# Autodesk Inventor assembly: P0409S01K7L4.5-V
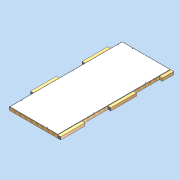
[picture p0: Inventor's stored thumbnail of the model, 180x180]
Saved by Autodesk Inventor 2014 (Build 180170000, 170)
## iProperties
Created: 2011-04
Part Number: P0409S01K7L4.5-V
Document SubType Name: Assembly
Designer: david.appleford
Description: 1w x 2.25w 01 Panel - 7 Locks 4.5 Lugs
Mass: 51000 g
Surface Area: 75539.4 cm^2
Volume: 258132 cm^3
Density: 0.197573 g/cm^3
Cost Center: £173.00
Justset: False
Title: 1w x 2.25w 01 Panel - 7 Locks 4.5 Lugs
Author: david.appleford
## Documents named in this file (5)
- C:\Documents and Settings\john.everitt\Local Settings\My Documents\Vault\Production MkII\VIRTUAL ELEMENTS\Virtual Walls\Virtual Timber + MgO\P0409S01K7L4.5-V.iam
- C:\Documents and Settings\john.everitt\Local Settings\My Documents\Vault\Production MkII\VIRTUAL ELEMENTS\Virtual Lugs\Superceded Lugs\LA02C3V.ipt
- C:\Documents and Settings\john.everitt\Local Settings\My Documents\Vault\Production MkII\VIRTUAL ELEMENTS\Virtual Lugs\Superceded Lugs\LA02M3V.ipt
- C:\Documents and Settings\john.everitt\Local Settings\My Documents\Vault\Production MkII\Virtual Elements\Virtual Walls\Virtual Timber + MgO\P0409S01K7-V.ipt
- C:\Documents and Settings\john.everitt\Local Settings\My Documents\Vault\Production MkII\VIRTUAL ELEMENTS\Virtual Lugs\Superceded Lugs\LA01C3V.ipt
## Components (6 placed, 4 different names)
1. P0409S01K7-V:1 — Mate:1, Flush:1, Flush:2, Mate:5, Mate:6, Flush:9, Flush:10, Mate:7, Flush:11, Mate:14, Flush:12, Flush:13
2. LA02C3V:1 — Mate:1, Flush:1, Flush:2, Mate:9, Mate:13
3. LA02M3V:5 — Mate:6, Flush:9, Mate:12
4. LA02M3V:2 — Mate:5, Flush:10, Mate:12, Mate:13
5. LA02M3V:4 — Mate:7, Flush:11, Mate:9
6. LA01C3V:1 — Mate:14, Flush:12, Flush:13
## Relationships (15: Mate 8, Flush 7)
- Mate:1: P0409S01K7-V:1 ↔ LA02C3V:1
- Flush:1: P0409S01K7-V:1 ↔ LA02C3V:1
- Flush:2: P0409S01K7-V:1 ↔ LA02C3V:1
- Mate:5: P0409S01K7-V:1 ↔ LA02M3V:2
- Mate:6: P0409S01K7-V:1 ↔ LA02M3V:5
- Flush:9: P0409S01K7-V:1 ↔ LA02M3V:5
- Flush:10: P0409S01K7-V:1 ↔ LA02M3V:2
- Mate:7: P0409S01K7-V:1 ↔ LA02M3V:4
- Flush:11: P0409S01K7-V:1 ↔ LA02M3V:4
- Mate:9: LA02C3V:1 ↔ LA02M3V:4
- Mate:12: LA02M3V:5 ↔ LA02M3V:2
- Mate:13: LA02C3V:1 ↔ LA02M3V:2
- Mate:14: P0409S01K7-V:1 ↔ LA01C3V:1
- Flush:12: P0409S01K7-V:1 ↔ LA01C3V:1
- Flush:13: P0409S01K7-V:1 ↔ LA01C3V:1
## Named parameters: t = 1 mm, Cl = 2 mm
